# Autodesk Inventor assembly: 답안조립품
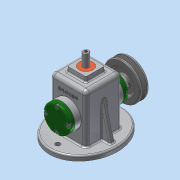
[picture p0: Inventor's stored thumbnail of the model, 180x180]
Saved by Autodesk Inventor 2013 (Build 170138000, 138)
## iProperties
Created: 2017-07
Part Number: 답안조립품
Document SubType Name: Assembly
Designer: dgall
Author: dgall
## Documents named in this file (16)
- C:\Users\dgall\Desktop\470707V1020\답안조립품.iam
- C:\Users\dgall\Desktop\470707V1020\본체.ipt
- C:\Users\dgall\Desktop\470707V1020\뒤커버.ipt
- C:\Users\dgall\Desktop\470707V1020\앞커버.ipt
- C:\Users\dgall\Desktop\470707V1020\편심축.ipt
- C:\Users\dgall\Desktop\470707V1020\베어링 12 x 32 x 10.ipt
- C:\Users\dgall\Desktop\470707V1020\오일실 12 25 7.ipt
- C:\Users\dgall\Desktop\470707V1020\키 4 x 4 x 10.ipt
- C:\Users\dgall\Desktop\470707V1020\V벨트풀리.ipt
- C:\Users\dgall\Desktop\470707V1020\멈춤나사 M3x8.ipt
- C:\Users\dgall\Desktop\470707V1020\링크.ipt
- C:\Users\dgall\Desktop\470707V1020\고정핀 1.2 x  8.ipt
- C:\Users\dgall\Desktop\470707V1020\핀 5 x 18.ipt
- C:\Users\dgall\Desktop\470707V1020\슬라이드.ipt
- C:\Users\dgall\Desktop\470707V1020\부시.ipt
- C:\Users\dgall\Desktop\470707V1020\볼트 M4 x 12.ipt
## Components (3 placed, 3 different names)
1. V벨트풀리:1 — 각도:2
2. 고정핀 1.2 x  8:1
3. 핀 5 x 18:1
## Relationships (1: Angle 1)
- 각도:2 [Angle]: V벨트풀리:1
